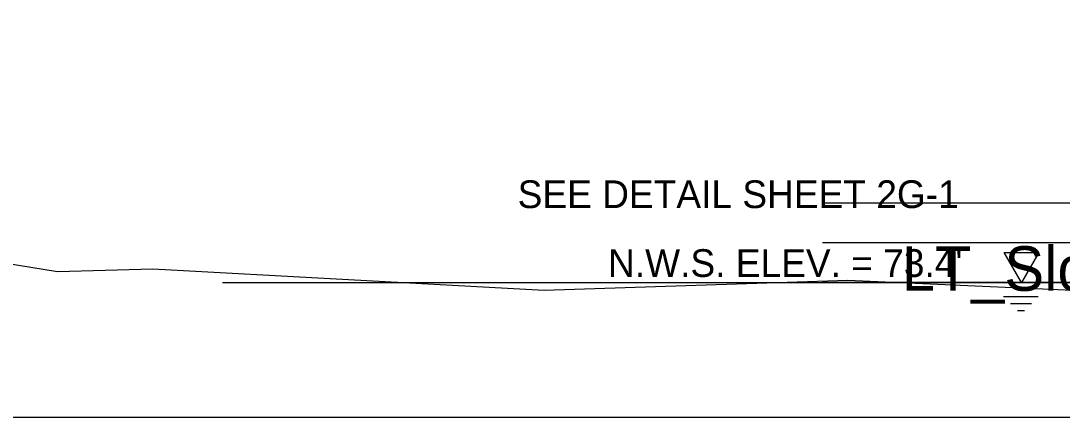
# Model space of a CAD drawing. Extents: x -14026 to 1303, y -10 to 9533.
# Drawn here: x 82.12 to 108.4, y 6500 to 6510.01 of the extents above; entities that cross this region are included whole.
import ezdxf

# ---------------------------------------------------------------- set-up
doc = ezdxf.new("R2010")
doc.units = 0
for name, color, linetype in [('Exist Cross Section Cell', 7, 'Continuous'), ('Exist XS Ground Line', 7, 'Continuous'), ('Old_Level_10', 7, 'Continuous'), ('Prop XS Side Slope Text', 7, 'Continuous'), ('Scratch_Level_0', 7, 'Continuous'), ('Scratch_Level_1', 7, 'Continuous'), ('Scratch_Level_3', 7, 'Continuous')]:
    doc.layers.add(name, color=color, linetype=linetype)

msp = doc.modelspace()

# ---------------------------------------------------------------- linework, layer by layer
at = {"layer": 'Exist Cross Section Cell'}
msp.add_line((0, 6500), (150, 6500), dxfattribs=at)
at = {"layer": 'Exist XS Ground Line'}
msp.add_lwpolyline([(78.639, 6504.395), (83.044, 6503.682), (85.453, 6503.747), (95.323, 6503.21), (102.994, 6503.456), (121.148, 6502.654), (127.718, 6505.729), (132.067, 6507.655), (138.73, 6509.387), (139.545, 6509.614), (139.942, 6509.603), (143.097, 6509.5), (143.478, 6509.583), (145.202, 6510.007)], dxfattribs=at)
at = {"layer": 'Prop XS Side Slope Text'}
for p, q in [((106.921, 6503.046), (107.796, 6503.046)), ((107.096, 6502.871), (107.621, 6502.871)), ((107.271, 6502.696), (107.446, 6502.696))]:
    msp.add_line(p, q, dxfattribs=at)
msp.add_lwpolyline([(106.934, 6504.159), (107.809, 6504.159), (107.371, 6503.4)], close=True, dxfattribs=at)
at = {"layer": 'Scratch_Level_1'}
msp.add_line((87.209, 6503.4), (136.682, 6503.4), dxfattribs=at)
at = {"layer": 'Scratch_Level_3'}
for p, q in [((127.015, 6505.4), (102.353, 6505.4)), ((124.879, 6504.4), (102.353, 6504.4)), ((109.616, 6503.4), (102.353, 6503.4))]:
    msp.add_line(p, q, dxfattribs=at)

# ---------------------------------------------------------------- texts
at = {"layer": 'Old_Level_10'}
msp.add_text('SEE DETAIL SHEET 2G-1', height=0.7, dxfattribs=at).set_placement((94.657, 6505.279))
at = {"layer": 'Prop XS Side Slope Text'}
msp.add_text("N.W.S. ELEV. = 73.4'", height=0.7, dxfattribs=at).set_placement((96.938, 6503.541))
at = {"layer": 'Scratch_Level_0'}
msp.add_text('LT_Slope_Fill', height=1.125, dxfattribs=at).set_placement((104.349, 6503.191))

doc.saveas('drawing.dxf')
